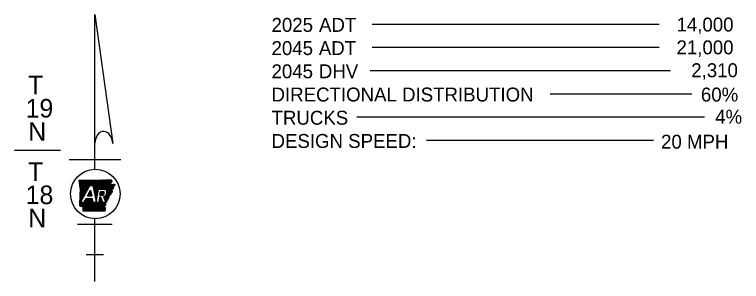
# Model space of a CAD drawing. Extents: x 670147 to 673275, y 705573 to 707613.
# Drawn here: x 672229 to 673167, y 706259 to 706604 of the extents above; entities that cross this region are included whole.
import ezdxf

# ---------------------------------------------------------------- set-up
doc = ezdxf.new("R2010")
doc.units = 0
for name, color, linetype in [('Default', 7, 'Continuous'), ('R_Draft', 7, 'Continuous'), ('R_Water Annot', 7, 'Continuous')]:
    doc.layers.add(name, color=color, linetype=linetype)

msp = doc.modelspace()

# ---------------------------------------------------------------- linework, layer by layer
at = {"layer": 'Default'}
for p, q in [((672690.39, 706591.66), (673060.91, 706591.66)), ((672690.44, 706561.66), (673060.91, 706561.66)), ((672687.57, 706531.66), (673075.36, 706531.66)), ((672920.39, 706501.66), (673103.25, 706501.66)), ((672670.39, 706471.66), (673119.41, 706471.66)), ((672760.39, 706441.66), (673053.65, 706441.66)), ((672228.51, 706428.75), (672287.93, 706428.75))]:
    msp.add_line(p, q, dxfattribs=at)
at = {"layer": 'R_Draft'}
for p, q in [((672332.27, 706604.04), (672355.34, 706437.36)), ((672332.27, 706404.16), (672332.27, 706604.04)), ((672298.89, 706416.52), (672365.64, 706416.52)), ((672313.59, 706361.29), (672325.91, 706383.06)), ((672325.91, 706383.06), (672329.57, 706383.06)), ((672322.65, 706369.84), (672326.68, 706376.96)), ((672337.01, 706378.52), (672345.57, 706378.52)), ((672339.67, 706375.45), (672343.69, 706375.45)), ((672320.4, 706365.86), (672317.81, 706361.29)), ((672329.06, 706365.86), (672320.4, 706365.86)), ((672322.65, 706369.84), (672328.21, 706369.84)), ((672339.9, 706368.22), (672338.41, 706368.22)), ((672338.86, 706370.8), (672342.53, 706370.8)), ((672342.45, 706361.29), (672339.9, 706368.22)), ((672343.52, 706368.58), (672346.21, 706361.29)), ((672317.81, 706361.29), (672313.59, 706361.29)), ((672337.21, 706361.29), (672330.03, 706361.29)), ((672346.21, 706361.29), (672342.45, 706361.29)), ((672332.27, 706259.1), (672332.27, 706340.22)), ((672310.02, 706333.33), (672354.52, 706333.33)), ((672321.14, 706293.81), (672343.4, 706293.81))]:
    msp.add_line(p, q, dxfattribs=at)
for points in [[(672311.98, 706390.11), (672324.17, 706390.11), (672334.88, 706390.13), (672347.49, 706390.33), (672353.34, 706390.46)], [(672313.33, 706371.17), (672313.55, 706377.59), (672311.98, 706390.11)], [(672311.99, 706390.12), (672324.18, 706390.11), (672334.87, 706390.13), (672347.49, 706390.33), (672353.34, 706390.46)], [(672312.87, 706357.14), (672313.55, 706377.59), (672311.99, 706390.12)], [(672329.57, 706383.06), (672334.11, 706361.87), (672337.01, 706378.52)], [(672357.17, 706384.86), (672358.23, 706383.76), (672355.6, 706381.6), (672355.88, 706379.42), (672353.62, 706377.93), (672354.4, 706374.58), (672352.66, 706372.99), (672352.5, 706371.26), (672350.39, 706370.5), (672350.06, 706367.25), (672348.54, 706365.62), (672347.81, 706363.17), (672345.59, 706361.15), (672345.76, 706357.58), (672344.26, 706355.89), (672345.63, 706352.83), (672344.68, 706349.78)], [(672351.53, 706384.58), (672357.25, 706384.87)], [(672351.53, 706384.58), (672357.25, 706384.87)], [(672326.68, 706376.96), (672328.21, 706369.84)], [(672338.86, 706370.8), (672339.67, 706375.45)], [(672312.87, 706357.14), (672313.33, 706371.17)], [(672330.03, 706361.29), (672329.06, 706365.86)], [(672338.41, 706368.22), (672337.21, 706361.29)], [(672344.68, 706349.78), (672317.05, 706349.83), (672317.04, 706355.93)], [(672344.68, 706349.78), (672317.05, 706349.83), (672317.04, 706355.92)]]:
    msp.add_lwpolyline(points, dxfattribs=at)
for centre, major_axis, ratio, start_param, end_param in [((672343.79, 706437), (-0.49, 16.02), 0.719778, 4.712385, 7.768526), ((672341.66, 706373.49), (-2.83, 0), 0.999987, 1.887169, 3.90762), ((672342.38, 706374), (-5.53, 0), 0.999987, 1.777838, 4.099264)]:
    msp.add_ellipse(centre, major_axis=major_axis, ratio=ratio, start_param=start_param, end_param=end_param, dxfattribs=at)
msp.add_ellipse((672332.79, 706372.19), major_axis=(31.98, 0), ratio=0.999976, dxfattribs=at)
for points in [[(672353.34, 706390.46), (672353.38, 706390.13), (672353.48, 706389.96), (672353.49, 706389.64), (672353.63, 706389.5), (672353.85, 706389.37), (672354.04, 706389.15), (672354.09, 706388.9), (672354.02, 706388.64), (672354.01, 706388.33), (672353.98, 706388.08), (672353.93, 706387.85), (672353.76, 706387.66), (672353.58, 706387.53), (672353.43, 706387.37), (672353.31, 706387.2), (672353.12, 706387.02), (672352.92, 706386.83), (672352.75, 706386.67), (672352.6, 706386.45), (672352.52, 706386.22), (672352.35, 706386.05), (672352.22, 706385.9), (672352.04, 706385.7), (672351.95, 706385.5), (672351.78, 706385.26), (672351.73, 706385.04), (672351.62, 706384.86), (672351.61, 706384.83)], [(672353.34, 706390.46), (672353.38, 706390.13), (672353.48, 706389.96), (672353.5, 706389.64), (672353.63, 706389.51), (672353.85, 706389.37), (672354.04, 706389.15), (672354.09, 706388.9), (672354.03, 706388.63), (672354.01, 706388.34), (672353.98, 706388.08), (672353.94, 706387.85), (672353.76, 706387.66), (672353.58, 706387.52), (672353.42, 706387.37), (672353.31, 706387.2), (672353.11, 706387.02), (672352.92, 706386.83), (672352.76, 706386.66), (672352.6, 706386.45), (672352.53, 706386.22), (672352.35, 706386.05), (672352.22, 706385.9), (672352.04, 706385.7), (672351.95, 706385.5), (672351.77, 706385.26), (672351.74, 706385.04), (672351.62, 706384.86), (672351.61, 706384.83)], [(672357.17, 706384.86), (672357.25, 706384.87), (672357.51, 706384.6), (672357.62, 706384.37), (672357.79, 706384.25), (672357.98, 706384.18), (672358.12, 706384), (672358.22, 706383.81), (672358.17, 706383.65), (672357.95, 706383.63), (672357.72, 706383.6), (672357.49, 706383.6), (672357.31, 706383.45), (672357.48, 706383.25), (672357.7, 706383.06), (672357.76, 706382.86), (672357.64, 706382.66), (672357.39, 706382.56), (672357.16, 706382.46), (672356.95, 706382.29), (672356.85, 706382.11), (672356.62, 706382.04), (672356.38, 706381.97), (672356.17, 706381.95), (672355.93, 706381.9), (672355.69, 706381.78), (672355.6, 706381.59), (672355.63, 706381.32), (672355.62, 706381.02), (672355.86, 706380.92), (672356.08, 706380.91), (672356.3, 706380.8), (672356.27, 706380.64), (672356.11, 706380.42), (672355.93, 706380.26), (672355.74, 706380.18), (672355.56, 706380.01), (672355.63, 706379.85), (672355.78, 706379.76), (672355.9, 706379.58), (672355.88, 706379.42), (672355.7, 706379.31), (672355.5, 706379.35), (672355.36, 706379.54), (672355.2, 706379.6), (672355.05, 706379.67), (672354.89, 706379.57), (672354.89, 706379.35), (672354.83, 706379.12), (672354.88, 706378.95), (672354.94, 706378.71), (672354.93, 706378.53), (672354.88, 706378.27), (672354.75, 706378), (672354.6, 706377.92), (672354.53, 706378.21), (672354.51, 706378.44), (672354.42, 706378.58), (672354.3, 706378.58), (672354.14, 706378.47), (672353.97, 706378.3), (672353.75, 706378.11), (672353.62, 706377.92), (672353.69, 706377.69), (672353.85, 706377.63), (672353.98, 706377.67), (672354.05, 706377.82), (672354.17, 706377.84), (672354.3, 706377.61)], [(672354.3, 706377.61), (672354.33, 706377.39), (672354.2, 706377.16), (672354.15, 706376.93), (672354.17, 706376.69), (672353.93, 706376.56), (672353.72, 706376.41), (672353.85, 706376.23), (672354.08, 706376.07), (672354.3, 706375.94), (672354.44, 706375.81), (672354.48, 706375.5), (672354.52, 706375.3), (672354.59, 706375.03), (672354.62, 706374.84), (672354.49, 706374.62), (672354.33, 706374.57), (672354.16, 706374.62), (672353.97, 706374.64), (672353.81, 706374.5), (672353.7, 706374.28), (672353.58, 706374.07), (672353.49, 706373.89), (672353.41, 706373.69), (672353.25, 706373.46), (672353.05, 706373.43), (672352.81, 706373.37), (672352.66, 706373.2), (672352.69, 706372.92), (672352.82, 706372.74), (672352.93, 706372.5), (672353, 706372.3), (672352.97, 706372.04), (672352.86, 706371.85), (672352.72, 706371.74), (672352.66, 706371.5), (672352.56, 706371.31), (672352.47, 706371.25), (672352.29, 706371.27), (672352.1, 706371.31), (672351.93, 706371.29), (672351.78, 706371.21), (672351.61, 706371.26), (672351.45, 706371.45), (672351.31, 706371.58), (672351.16, 706371.63), (672351, 706371.55), (672350.98, 706371.3), (672351.05, 706371.05), (672351.12, 706370.7), (672351.05, 706370.49), (672351.03, 706370.14)], [(672346.85, 706363), (672346.83, 706363), (672346.69, 706362.82), (672346.77, 706362.56), (672347.06, 706362.45), (672347.2, 706362.2), (672347.2, 706361.97), (672347.11, 706361.66), (672346.97, 706361.52), (672346.71, 706361.46), (672346.51, 706361.42), (672346.48, 706361.07), (672346.38, 706360.9), (672346.23, 706360.85), (672346, 706360.96), (672345.86, 706361.02), (672345.7, 706361.09), (672345.49, 706361.21), (672345.32, 706361.19), (672345.37, 706360.86), (672345.39, 706360.85), (672345.57, 706360.6), (672345.75, 706360.4), (672345.83, 706360.17)], [(672346.85, 706363), (672346.83, 706363), (672346.69, 706362.82), (672346.77, 706362.56), (672347.06, 706362.45), (672347.2, 706362.2), (672347.2, 706361.97), (672347.11, 706361.66), (672346.97, 706361.52), (672346.71, 706361.46), (672346.51, 706361.42), (672346.48, 706361.07), (672346.38, 706360.9), (672346.23, 706360.85), (672346, 706360.96), (672345.86, 706361.02), (672345.7, 706361.09), (672345.49, 706361.21), (672345.32, 706361.19), (672345.37, 706360.86), (672345.39, 706360.85), (672345.57, 706360.6), (672345.75, 706360.4), (672345.83, 706360.17)], [(672351.03, 706370.14), (672350.76, 706369.94), (672350.64, 706369.73), (672349.97, 706369.79), (672349.99, 706369.56), (672349.75, 706369.43), (672349.54, 706369.28), (672349.66, 706369.1), (672349.89, 706368.93), (672350.12, 706368.81), (672350.26, 706368.68), (672350.29, 706368.36), (672350.34, 706368.17), (672350.41, 706367.9), (672350.44, 706367.71), (672350.3, 706367.49), (672350.14, 706367.44), (672349.98, 706367.49), (672349.78, 706367.51), (672349.63, 706367.36), (672349.51, 706367.15), (672349.4, 706366.93), (672349.32, 706366.75), (672349.23, 706366.56), (672349.07, 706366.33), (672348.87, 706366.3), (672348.62, 706366.23), (672348.48, 706366.07), (672348.5, 706365.79), (672348.64, 706365.6), (672348.74, 706365.37), (672348.82, 706365.16), (672348.79, 706364.91), (672348.68, 706364.72), (672348.54, 706364.6), (672348.48, 706364.36), (672348.38, 706364.18), (672348.29, 706364.12), (672348.11, 706364.14), (672347.92, 706364.18), (672347.75, 706364.16), (672347.59, 706364.08), (672347.43, 706364.13), (672347.27, 706364.31), (672347.13, 706364.45), (672346.98, 706364.5), (672346.82, 706364.42), (672346.79, 706364.17), (672346.87, 706363.92), (672346.94, 706363.56), (672346.87, 706363.36), (672346.85, 706363)], [(672317.04, 706355.93), (672317.07, 706355.91), (672316.93, 706356.01), (672316.73, 706356.1), (672316.51, 706356.12), (672316.23, 706356.16), (672316, 706356.18), (672315.76, 706356.34), (672315.5, 706356.18), (672315.21, 706356.05), (672315.05, 706356.19), (672314.83, 706356.1), (672314.68, 706356.15), (672314.42, 706355.96), (672314.16, 706356.03), (672313.99, 706355.98), (672313.76, 706355.98), (672313.71, 706356.24), (672313.49, 706356.28), (672313.3, 706356.38), (672313.18, 706356.65), (672313.08, 706356.85), (672312.87, 706357.14)], [(672317.04, 706355.92), (672317.07, 706355.91), (672316.92, 706356.01), (672316.73, 706356.11), (672316.51, 706356.12), (672316.23, 706356.16), (672316, 706356.18), (672315.76, 706356.34), (672315.5, 706356.17), (672315.21, 706356.05), (672315.05, 706356.19), (672314.83, 706356.1), (672314.68, 706356.14), (672314.41, 706355.96), (672314.17, 706356.03), (672313.98, 706355.98), (672313.76, 706355.98), (672313.71, 706356.24), (672313.49, 706356.28), (672313.31, 706356.38), (672313.18, 706356.65), (672313.09, 706356.85), (672312.87, 706357.14)], [(672345.83, 706360.17), (672345.76, 706359.99), (672345.67, 706359.69), (672345.7, 706359.44), (672345.81, 706359.22), (672345.99, 706359.1), (672346.19, 706358.93), (672346.17, 706358.66), (672346.06, 706358.57), (672345.79, 706358.63), (672345.59, 706358.72), (672345.42, 706358.67), (672345.19, 706358.56), (672345.01, 706358.53), (672345.02, 706358.17), (672345.25, 706357.91), (672345.45, 706357.91), (672345.69, 706357.88), (672345.77, 706357.61), (672345.63, 706357.38), (672345.41, 706357.27), (672345.12, 706357.41), (672344.92, 706357.55), (672344.72, 706357.69), (672344.46, 706357.76), (672344.32, 706357.73), (672344.25, 706357.41), (672344.37, 706357.12), (672344.56, 706356.92), (672344.74, 706356.67), (672344.72, 706356.48), (672344.58, 706356.43), (672344.34, 706356.38), (672344.2, 706356.3), (672344.16, 706356.24), (672344.24, 706355.98), (672344.3, 706355.71), (672344.3, 706355.49), (672344.22, 706355.3), (672344.09, 706355), (672344.11, 706354.81), (672344.2, 706354.71), (672344.31, 706354.74), (672344.46, 706354.85), (672344.56, 706354.97), (672344.64, 706355.12), (672344.8, 706355.25), (672344.99, 706355.13), (672345.04, 706354.9), (672344.93, 706354.7), (672344.77, 706354.6), (672344.58, 706354.53), (672344.43, 706354.37), (672344.47, 706354.17), (672344.58, 706354.06), (672344.86, 706354.12), (672345.05, 706354.2), (672345.16, 706354.3), (672345.28, 706354.43), (672345.35, 706354.56), (672345.45, 706354.7), (672345.62, 706354.73), (672345.71, 706354.62), (672345.67, 706354.37), (672345.57, 706354.12), (672345.42, 706353.92), (672345.27, 706353.78), (672345.07, 706353.47), (672345.11, 706353.18), (672345.19, 706352.94), (672345.29, 706352.77), (672345.47, 706352.8), (672345.67, 706352.83), (672345.79, 706352.73), (672345.78, 706352.52), (672345.63, 706352.31), (672345.49, 706352.12), (672345.41, 706351.85), (672345.44, 706351.65), (672345.44, 706351.49), (672345.38, 706351.29), (672345.28, 706351.19), (672344.99, 706351.19), (672344.7, 706351.23), (672344.55, 706351.14), (672344.58, 706350.88), (672344.74, 706350.69), (672344.87, 706350.6), (672345.04, 706350.38), (672345.11, 706350.21), (672345.09, 706350.06), (672344.98, 706349.93), (672344.68, 706349.78)], [(672345.83, 706360.17), (672345.76, 706359.99), (672345.67, 706359.69), (672345.7, 706359.44), (672345.81, 706359.22), (672345.99, 706359.1), (672346.19, 706358.93), (672346.17, 706358.66), (672346.06, 706358.57), (672345.79, 706358.63), (672345.59, 706358.72), (672345.42, 706358.67), (672345.19, 706358.56), (672345.01, 706358.53), (672345.02, 706358.17), (672345.25, 706357.91), (672345.45, 706357.91), (672345.69, 706357.88), (672345.77, 706357.61), (672345.63, 706357.38), (672345.41, 706357.27), (672345.12, 706357.41), (672344.92, 706357.55), (672344.72, 706357.69), (672344.46, 706357.76), (672344.32, 706357.73), (672344.25, 706357.41), (672344.37, 706357.12), (672344.56, 706356.92), (672344.74, 706356.67), (672344.72, 706356.48), (672344.58, 706356.43), (672344.34, 706356.38), (672344.2, 706356.3), (672344.16, 706356.24), (672344.24, 706355.98), (672344.3, 706355.71), (672344.3, 706355.49), (672344.22, 706355.3), (672344.09, 706355), (672344.11, 706354.81), (672344.2, 706354.71), (672344.31, 706354.74), (672344.46, 706354.85), (672344.56, 706354.97), (672344.64, 706355.12), (672344.8, 706355.25), (672344.99, 706355.13), (672345.04, 706354.9), (672344.93, 706354.7), (672344.77, 706354.6), (672344.58, 706354.53), (672344.43, 706354.37), (672344.47, 706354.17), (672344.58, 706354.06), (672344.86, 706354.12), (672345.05, 706354.2), (672345.16, 706354.3), (672345.28, 706354.43), (672345.35, 706354.56), (672345.45, 706354.7), (672345.62, 706354.73), (672345.71, 706354.62), (672345.67, 706354.37), (672345.57, 706354.12), (672345.42, 706353.92), (672345.27, 706353.78), (672345.07, 706353.47), (672345.11, 706353.18), (672345.19, 706352.94), (672345.29, 706352.77), (672345.47, 706352.8), (672345.67, 706352.83), (672345.79, 706352.73), (672345.78, 706352.52), (672345.63, 706352.31), (672345.49, 706352.12), (672345.41, 706351.85), (672345.44, 706351.65), (672345.44, 706351.49), (672345.38, 706351.29), (672345.28, 706351.19), (672344.99, 706351.19), (672344.7, 706351.23), (672344.55, 706351.14), (672344.58, 706350.88), (672344.74, 706350.69), (672344.87, 706350.6), (672345.04, 706350.38), (672345.11, 706350.21), (672345.09, 706350.06), (672344.98, 706349.93), (672344.68, 706349.78)]]:
    msp.add_spline(points, degree=3, dxfattribs=at)
at = {"layer": 'R_Water Annot'}
for p, q in [((672312.02, 706389.84), (672312.3, 706390.12)), ((672312.12, 706389.06), (672313.18, 706390.12)), ((672312.22, 706388.27), (672314.06, 706390.12)), ((672312.31, 706387.48), (672314.95, 706390.12)), ((672312.41, 706386.7), (672315.83, 706390.11)), ((672312.51, 706385.91), (672316.71, 706390.11)), ((672312.61, 706385.13), (672317.59, 706390.11)), ((672312.71, 706384.34), (672318.48, 706390.11)), ((672312.8, 706383.56), (672319.36, 706390.11)), ((672312.9, 706382.77), (672320.24, 706390.11)), ((672313, 706381.98), (672321.13, 706390.11)), ((672313.1, 706381.2), (672322.01, 706390.11)), ((672313.2, 706380.41), (672322.89, 706390.11)), ((672313.29, 706379.63), (672323.78, 706390.11)), ((672313.29, 706369.91), (672325.21, 706381.83)), ((672313.32, 706370.82), (672332.63, 706390.13)), ((672313.35, 706371.74), (672331.74, 706390.13)), ((672313.38, 706372.65), (672330.86, 706390.12)), ((672313.39, 706378.84), (672324.66, 706390.11)), ((672313.41, 706373.56), (672329.97, 706390.12)), ((672313.44, 706374.48), (672329.09, 706390.12)), ((672313.47, 706375.39), (672328.2, 706390.12)), ((672313.49, 706378.06), (672325.54, 706390.11)), ((672313.5, 706376.31), (672327.32, 706390.12)), ((672313.53, 706377.22), (672326.43, 706390.11)), ((672326.44, 706383.06), (672333.51, 706390.13)), ((672327.33, 706383.06), (672334.4, 706390.13)), ((672328.21, 706383.06), (672335.29, 706390.14)), ((672329.09, 706383.06), (672336.19, 706390.15)), ((672329.64, 706382.73), (672337.08, 706390.17)), ((672329.8, 706382), (672337.98, 706390.18)), ((672329.96, 706381.27), (672338.88, 706390.19)), ((672330.11, 706380.54), (672339.78, 706390.21)), ((672330.27, 706379.81), (672340.67, 706390.22)), ((672330.42, 706379.09), (672341.57, 706390.24)), ((672330.58, 706378.36), (672342.47, 706390.25)), ((672330.73, 706377.63), (672343.37, 706390.26)), ((672330.89, 706376.9), (672344.26, 706390.28)), ((672331.05, 706376.18), (672345.16, 706390.29)), ((672331.2, 706375.45), (672346.06, 706390.31)), ((672331.36, 706374.72), (672346.96, 706390.32)), ((672331.51, 706373.99), (672347.86, 706390.34)), ((672331.67, 706373.26), (672348.76, 706390.36)), ((672337.81, 706378.52), (672349.67, 706390.38)), ((672338.69, 706378.52), (672350.57, 706390.4)), ((672339.57, 706378.52), (672351.48, 706390.42)), ((672340.46, 706378.52), (672352.38, 706390.44)), ((672341.34, 706378.52), (672353.28, 706390.46)), ((672342.22, 706378.52), (672353.48, 706389.78)), ((672343.11, 706378.52), (672353.91, 706389.32)), ((672343.99, 706378.52), (672354.02, 706388.55)), ((672344.87, 706378.52), (672352.01, 706385.65)), ((672345.68, 706378.44), (672351.83, 706384.59)), ((672346.16, 706378.04), (672352.76, 706384.64)), ((672346.59, 706377.58), (672353.69, 706384.69)), ((672346.97, 706377.08), (672354.63, 706384.74)), ((672347.3, 706376.53), (672355.56, 706384.78)), ((672347.57, 706375.91), (672356.49, 706384.83)), ((672347.77, 706375.23), (672357.33, 706384.79)), ((672347.89, 706374.47), (672357.74, 706384.32)), ((672347.9, 706373.59), (672355.63, 706381.32)), ((672357.35, 706383.04), (672358.15, 706383.84)), ((672313.17, 706366.25), (672320.6, 706373.68)), ((672313.2, 706367.17), (672321.75, 706375.72)), ((672313.23, 706368.08), (672322.91, 706377.76)), ((672313.26, 706368.99), (672324.06, 706379.79)), ((672322.69, 706369.84), (672327.23, 706374.38)), ((672323.58, 706369.84), (672327.39, 706373.65)), ((672323.75, 706371.77), (672327.08, 706375.1)), ((672324.46, 706369.84), (672327.55, 706372.92)), ((672324.9, 706373.81), (672326.92, 706375.83)), ((672325.34, 706369.84), (672327.7, 706372.19)), ((672326.06, 706375.85), (672326.77, 706376.56)), ((672331.82, 706372.54), (672336.84, 706377.55)), ((672331.98, 706371.81), (672336.65, 706376.48)), ((672332.14, 706371.08), (672336.46, 706375.41)), ((672332.29, 706370.35), (672336.28, 706374.34)), ((672332.45, 706369.63), (672336.09, 706373.27)), ((672332.6, 706368.9), (672335.91, 706372.2)), ((672338.87, 706370.8), (672343.52, 706375.45)), ((672339.05, 706371.86), (672342.63, 706375.45)), ((672339.24, 706372.93), (672341.75, 706375.45)), ((672339.42, 706374), (672340.87, 706375.45)), ((672339.61, 706375.07), (672339.98, 706375.45)), ((672339.75, 706370.8), (672344.01, 706375.05)), ((672340.64, 706370.8), (672344.31, 706374.47)), ((672341.52, 706370.8), (672344.47, 706373.75)), ((672342.4, 706370.8), (672344.4, 706372.79)), ((672344.07, 706367.11), (672353.86, 706376.9)), ((672344.3, 706366.46), (672354.03, 706376.18)), ((672344.54, 706365.82), (672354.19, 706375.47)), ((672344.78, 706365.17), (672354.36, 706374.75)), ((672346.95, 706370.87), (672353.7, 706377.62)), ((672347.71, 706372.52), (672355.73, 706380.54)), ((672351.34, 706370.84), (672352.58, 706372.08)), ((672354.74, 706378.67), (672355.83, 706379.76)), ((672313.02, 706361.68), (672314.83, 706363.5)), ((672313.05, 706362.6), (672315.99, 706365.54)), ((672313.08, 706363.51), (672317.14, 706367.57)), ((672313.11, 706364.43), (672318.29, 706369.61)), ((672313.14, 706365.34), (672319.45, 706371.65)), ((672313.21, 706356.57), (672322.5, 706365.86)), ((672313.74, 706356.22), (672323.38, 706365.86)), ((672314.37, 706355.97), (672324.26, 706365.86)), ((672315.42, 706356.13), (672325.15, 706365.86)), ((672316.32, 706356.15), (672326.03, 706365.86)), ((672317.01, 706355.96), (672326.91, 706365.86)), ((672317.04, 706354.22), (672328.68, 706365.86)), ((672317.04, 706355.1), (672327.8, 706365.86)), ((672317.04, 706353.34), (672329.15, 706365.44)), ((672317.05, 706352.46), (672329.3, 706364.71)), ((672317.05, 706351.58), (672329.46, 706363.99)), ((672317.05, 706350.69), (672329.61, 706363.26)), ((672317.06, 706349.83), (672329.77, 706362.53)), ((672318.82, 706363.06), (672321.61, 706365.86)), ((672319.97, 706365.1), (672320.73, 706365.86)), ((672325.89, 706349.81), (672341.08, 706365.01)), ((672326.23, 706369.84), (672327.86, 706371.47)), ((672326.77, 706349.81), (672341.32, 706364.36)), ((672327.11, 706369.84), (672328.01, 706370.74)), ((672327.65, 706349.81), (672341.56, 706363.72)), ((672328, 706369.84), (672328.17, 706370.01)), ((672328.53, 706349.81), (672341.8, 706363.07)), ((672329.41, 706349.81), (672342.04, 706362.43)), ((672332.76, 706368.17), (672335.72, 706371.13)), ((672332.91, 706367.44), (672335.53, 706370.06)), ((672333.07, 706366.71), (672335.35, 706368.99)), ((672333.23, 706365.99), (672335.16, 706367.92)), ((672333.38, 706365.26), (672334.97, 706366.85)), ((672333.54, 706364.53), (672334.79, 706365.78)), ((672333.69, 706363.8), (672334.6, 706364.71)), ((672333.85, 706363.08), (672334.41, 706363.64)), ((672334, 706362.35), (672334.23, 706362.57)), ((672337.36, 706362.17), (672340.84, 706365.65)), ((672337.55, 706363.24), (672340.61, 706366.3)), ((672337.73, 706364.31), (672340.37, 706366.94)), ((672337.92, 706365.38), (672340.13, 706367.59)), ((672338.11, 706366.45), (672339.87, 706368.22)), ((672338.29, 706367.52), (672338.99, 706368.22)), ((672343.59, 706368.4), (672343.86, 706368.67)), ((672343.83, 706367.75), (672345.51, 706369.43)), ((672345.02, 706364.53), (672350.32, 706369.83)), ((672345.26, 706363.88), (672350.22, 706368.84)), ((672345.5, 706363.24), (672350.12, 706367.86)), ((672345.73, 706362.59), (672348.44, 706365.3)), ((672345.97, 706361.95), (672348.07, 706364.04)), ((672312.88, 706357.13), (672317.05, 706361.29)), ((672312.9, 706358.03), (672316.16, 706361.29)), ((672312.93, 706358.94), (672315.28, 706361.29)), ((672312.96, 706359.86), (672314.4, 706361.29)), ((672312.99, 706360.77), (672313.68, 706361.46)), ((672317.95, 706349.82), (672329.93, 706361.8)), ((672318.83, 706349.82), (672330.3, 706361.29)), ((672319.71, 706349.82), (672331.18, 706361.29)), ((672320.59, 706349.82), (672332.07, 706361.29)), ((672321.48, 706349.82), (672332.95, 706361.29)), ((672322.36, 706349.82), (672333.83, 706361.29)), ((672323.24, 706349.82), (672334.72, 706361.29)), ((672324.12, 706349.81), (672335.6, 706361.29)), ((672325, 706349.81), (672336.48, 706361.29)), ((672330.3, 706349.8), (672342.27, 706361.78)), ((672331.18, 706349.8), (672342.67, 706361.29)), ((672332.06, 706349.8), (672343.55, 706361.29)), ((672332.94, 706349.8), (672344.44, 706361.29)), ((672333.82, 706349.8), (672345.32, 706361.29)), ((672334.71, 706349.8), (672345.61, 706360.71)), ((672335.59, 706349.8), (672345.65, 706359.86)), ((672336.47, 706349.79), (672345.69, 706359.02)), ((672337.35, 706349.79), (672345.73, 706358.17)), ((672338.23, 706349.79), (672344.28, 706355.84)), ((672339.12, 706349.79), (672344.55, 706355.23)), ((672340, 706349.79), (672344.83, 706354.62)), ((672340.88, 706349.79), (672345.1, 706354.01)), ((672341.76, 706349.79), (672345.37, 706353.4)), ((672342.65, 706349.78), (672345.6, 706352.74)), ((672343.53, 706349.78), (672345.2, 706351.46)), ((672344.41, 706349.78), (672344.8, 706350.17))]:
    msp.add_line(p, q, dxfattribs=at)

# ---------------------------------------------------------------- texts
at = {"layer": 'Default'}
for s, height, p in [('2025', 18, (672560.39, 706581.66)), (' ADT', 18, (672614.99, 706581.66)), ('14,000', 18, (673083.34, 706582.12)), ('2045', 18, (672560.39, 706551.66)), (' ADT', 18, (672614.78, 706551.66)), ('21,000', 18, (673083.34, 706552.59)), ('2,310', 18, (673102.35, 706523.06)), ('2045', 18, (672560.39, 706521.66)), (' DHV', 18, (672614.78, 706521.66)), ('T', 24, (672245.85, 706500.95)), ('DIRECTIONAL DISTRIBUTION', 18, (672560.39, 706491.66)), ('60%', 18, (673114.84, 706491.62)), ('19', 24, (672242.82, 706470.95)), ('TRUCKS', 18, (672560.39, 706461.66)), ('4%', 18, (673133.27, 706462.95)), ('N', 24, (672246.23, 706440.95)), ('DESIGN SPEED:', 18, (672560.39, 706431.66)), ('20 MPH', 18, (673063.38, 706430.71)), ('T', 24, (672245.85, 706389.07)), ('18', 24, (672242.92, 706359.07)), ('N', 24, (672246.23, 706329.07))]:
    msp.add_text(s, height=height, dxfattribs=at).set_placement(p)
at = {"layer": 'R_Draft'}
msp.add_text('STS 10-03-17', height=0.9245, dxfattribs=at).set_placement((672329.73, 706340.48))

doc.saveas('drawing.dxf')
